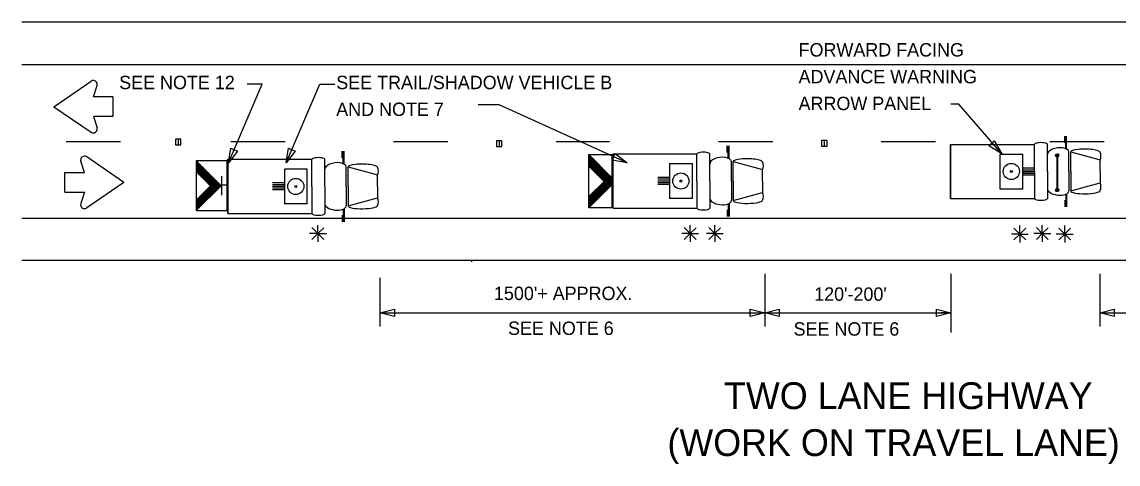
# Model space of a CAD drawing. Extents: x -747 to 834, y -5485 to -3577.
# Drawn here: x -746.8 to -256.3, y -4722 to -4524.1 of the extents above; entities that cross this region are included whole.
import ezdxf

# ---------------------------------------------------------------- set-up
doc = ezdxf.new("R2010")
doc.units = 0
doc.layers.add('Level 1', color=7, linetype='Continuous')
doc.layers.add('Working Level 1', color=7, linetype='Continuous')

msp = doc.modelspace()

# ---------------------------------------------------------------- linework, layer by layer
at = {"layer": 'Level 1'}
for points in [[(-654.31, -4587.26), (-639.27, -4552), (-645.96, -4552)], [(-628.59, -4587.26), (-613.54, -4552), (-606.86, -4552)], [(-476.04, -4587.26), (-533.3, -4561.2), (-542.63, -4561.2)]]:
    msp.add_lwpolyline(points, dxfattribs=at)
at = {"layer": 'Working Level 1'}
for p, q in [((-746.8, -4524.13), (52.95, -4524.13)), ((-746.8, -4543.26), (52.95, -4543.26)), ((-732.53, -4562.09), (-715.86, -4550.65)), ((-714.81, -4557.72), (-713.18, -4552.65)), ((-706.14, -4557.72), (-714.81, -4557.72)), ((-706.14, -4557.72), (-706.14, -4566.45)), ((-732.53, -4562.09), (-715.86, -4573.52)), ((-706.14, -4566.45), (-714.81, -4566.45)), ((-714.81, -4566.45), (-713.18, -4571.53)), ((-280.21, -4578.2), (-280.21, -4575.23)), ((-279.74, -4581.06), (-279.74, -4575.23)), ((-279.35, -4581.06), (-279.35, -4575.23)), ((-675.68, -4576.65), (-678.11, -4576.65)), ((-678.11, -4576.65), (-678.11, -4579.08)), ((-678.11, -4579.08), (-675.68, -4579.08)), ((-676.89, -4576.65), (-676.89, -4579.08)), ((-675.68, -4579.08), (-675.68, -4576.65)), ((-532, -4577.39), (-534.43, -4577.39)), ((-534.43, -4577.39), (-534.43, -4579.82)), ((-534.43, -4579.82), (-532, -4579.82)), ((-533.21, -4577.39), (-533.22, -4579.82)), ((-532, -4579.82), (-532, -4577.39)), ((-431.24, -4582.5), (-431.24, -4579.53)), ((-430.77, -4585.36), (-430.77, -4579.53)), ((-430.38, -4585.36), (-430.38, -4579.53)), ((-386.56, -4577.25), (-388.99, -4577.25)), ((-388.99, -4577.25), (-388.99, -4579.68)), ((-388.99, -4579.68), (-386.56, -4579.68)), ((-387.77, -4577.25), (-387.78, -4579.68)), ((-386.56, -4579.68), (-386.56, -4577.25)), ((-331.27, -4578.92), (-331.27, -4603.18)), ((-331.27, -4578.93), (-293.72, -4578.93)), ((-331.27, -4603.18), (-331.27, -4578.93)), ((-293.72, -4591.05), (-293.72, -4578.93)), ((-287.97, -4591.05), (-287.97, -4578.93)), ((-701.14, -4595.95), (-717.81, -4584.51)), ((-654.6, -4585.63), (-617.05, -4585.63)), ((-654.6, -4609.89), (-654.6, -4585.63)), ((-654.6, -4585.63), (-654.6, -4609.88)), ((-617.05, -4597.76), (-617.05, -4585.63)), ((-611.3, -4597.76), (-611.3, -4585.63)), ((-603.55, -4584.91), (-603.55, -4581.94)), ((-603.08, -4587.76), (-603.08, -4581.94)), ((-602.68, -4587.76), (-602.68, -4581.94)), ((-493.16, -4583.51), (-482.8, -4593.86)), ((-482.3, -4583.23), (-444.75, -4583.23)), ((-482.3, -4607.48), (-482.3, -4583.23)), ((-444.75, -4595.35), (-444.75, -4583.23)), ((-439, -4595.35), (-439, -4583.23)), ((-309.21, -4583.29), (-298.95, -4583.29)), ((-309.21, -4583.29), (-309.21, -4598.81)), ((-298.95, -4598.81), (-298.95, -4583.29)), ((-284.3, -4583.68), (-284.3, -4583.68)), ((-283.68, -4584.03), (-283.68, -4599.08)), ((-283.64, -4584.03), (-283.64, -4599.08)), ((-283.6, -4584.03), (-283.6, -4599.08)), ((-283.52, -4584.03), (-283.52, -4599.08)), ((-283.42, -4583.17), (-283.42, -4583.17)), ((-283.4, -4584.03), (-283.4, -4599.08)), ((-278.33, -4591.05), (-278.33, -4582.32)), ((-277.53, -4582.32), (-264.4, -4585.91)), ((-277.53, -4591.05), (-277.53, -4582.32)), ((-264.4, -4591.05), (-264.4, -4585.91)), ((-718.86, -4591.58), (-720.49, -4586.51)), ((-668.86, -4586.27), (-657.68, -4597.44)), ((-619.12, -4590), (-629.38, -4590)), ((-629.38, -4590), (-629.38, -4605.52)), ((-619.12, -4605.52), (-619.12, -4590)), ((-601.67, -4597.76), (-601.67, -4589.02)), ((-600.87, -4589.02), (-587.74, -4592.61)), ((-600.87, -4597.76), (-600.87, -4589.02)), ((-493.16, -4588.69), (-486.33, -4595.49)), ((-446.82, -4587.59), (-457.08, -4587.59)), ((-457.08, -4587.59), (-457.08, -4603.12)), ((-446.82, -4603.12), (-446.82, -4587.59)), ((-429.36, -4595.35), (-429.36, -4586.62)), ((-428.56, -4586.62), (-415.43, -4590.21)), ((-428.56, -4595.35), (-428.56, -4586.62)), ((-415.43, -4595.35), (-415.43, -4590.21)), ((-298.95, -4589.5), (-293.72, -4589.5)), ((-298.95, -4590.28), (-293.72, -4590.28)), ((-727.53, -4600.31), (-727.53, -4591.58)), ((-727.53, -4591.58), (-718.86, -4591.58)), ((-668.86, -4591.12), (-662.45, -4597.51)), ((-657.3, -4601.65), (-657.3, -4593.24)), ((-587.74, -4597.76), (-587.74, -4592.61)), ((-493.16, -4602.31), (-486.33, -4595.49)), ((-457.08, -4593.8), (-462.31, -4593.8)), ((-457.08, -4594.58), (-462.31, -4594.58)), ((-457.08, -4595.35), (-462.31, -4595.35)), ((-444.75, -4595.35), (-444.75, -4607.48)), ((-439, -4595.35), (-439, -4607.48)), ((-429.36, -4595.35), (-429.36, -4604.09)), ((-428.56, -4595.35), (-428.56, -4604.09)), ((-415.43, -4595.35), (-415.43, -4600.5)), ((-298.95, -4591.05), (-293.72, -4591.05)), ((-298.95, -4591.83), (-293.72, -4591.83)), ((-298.95, -4592.6), (-293.72, -4592.6)), ((-293.72, -4591.05), (-293.72, -4603.18)), ((-287.97, -4591.05), (-287.97, -4603.18)), ((-278.33, -4591.05), (-278.33, -4599.79)), ((-277.53, -4591.05), (-277.53, -4599.79)), ((-264.4, -4591.05), (-264.4, -4596.2)), ((-727.53, -4600.31), (-718.86, -4600.31)), ((-718.86, -4600.31), (-720.49, -4605.38)), ((-701.14, -4595.95), (-717.81, -4607.38)), ((-668.86, -4603.9), (-662.45, -4597.51)), ((-668.8, -4608.57), (-657.68, -4597.44)), ((-654.97, -4597.25), (-657.37, -4597.25)), ((-629.38, -4596.21), (-634.61, -4596.21)), ((-629.38, -4596.98), (-634.61, -4596.98)), ((-629.38, -4597.76), (-634.61, -4597.76)), ((-629.38, -4598.54), (-634.61, -4598.54)), ((-629.38, -4599.31), (-634.61, -4599.31)), ((-617.05, -4597.76), (-617.05, -4609.88)), ((-611.3, -4597.76), (-611.3, -4609.88)), ((-601.67, -4597.76), (-601.67, -4606.49)), ((-600.87, -4597.76), (-600.87, -4606.49)), ((-587.74, -4597.76), (-587.74, -4602.91)), ((-493.1, -4607.29), (-482.85, -4597.04)), ((-457.08, -4596.13), (-462.31, -4596.13)), ((-457.08, -4596.91), (-462.31, -4596.91)), ((-428.56, -4604.09), (-415.43, -4600.5)), ((-309.21, -4598.81), (-298.95, -4598.81)), ((-284.26, -4599.21), (-284.26, -4599.21)), ((-283.38, -4598.7), (-283.38, -4598.7)), ((-277.53, -4599.79), (-264.4, -4596.2)), ((-619.12, -4605.52), (-629.38, -4605.52)), ((-600.87, -4606.49), (-587.74, -4602.91)), ((-446.82, -4603.12), (-457.08, -4603.12)), ((-430.77, -4605.35), (-430.77, -4611.18)), ((-430.38, -4605.35), (-430.38, -4611.18)), ((-331.27, -4603.18), (-293.72, -4603.18)), ((-280.21, -4603.9), (-280.21, -4606.87)), ((-279.74, -4601.05), (-279.74, -4606.87)), ((-279.35, -4601.05), (-279.35, -4606.87)), ((-654.6, -4609.88), (-617.05, -4609.88)), ((-603.08, -4607.76), (-603.08, -4613.58)), ((-602.68, -4607.76), (-602.68, -4613.58)), ((-482.3, -4607.48), (-444.75, -4607.48)), ((-431.24, -4608.21), (-431.24, -4611.18)), ((-746.8, -4611.95), (52.95, -4611.95)), ((-614.35, -4618.83), (-614.35, -4615.06)), ((-603.55, -4610.61), (-603.55, -4613.58)), ((-447.75, -4618.83), (-447.75, -4615.06)), ((-436.78, -4618.83), (-436.78, -4615.06)), ((-300.25, -4619.07), (-300.25, -4615.3)), ((-290.23, -4618.83), (-290.23, -4615.06)), ((-280.2, -4619.07), (-280.2, -4615.3)), ((-614.35, -4618.83), (-618.11, -4618.83)), ((-614.35, -4618.83), (-617.01, -4616.17)), ((-614.35, -4618.83), (-617.01, -4621.49)), ((-614.41, -4618.88), (-611.75, -4616.22)), ((-614.35, -4618.83), (-611.69, -4621.49)), ((-614.35, -4618.83), (-614.35, -4622.59)), ((-614.35, -4618.83), (-610.59, -4618.83)), ((-447.75, -4618.83), (-451.52, -4618.83)), ((-447.75, -4618.83), (-450.41, -4616.17)), ((-447.75, -4618.83), (-450.41, -4621.49)), ((-447.82, -4618.88), (-445.15, -4616.22)), ((-447.75, -4618.83), (-445.09, -4621.49)), ((-447.75, -4618.83), (-447.75, -4622.59)), ((-447.75, -4618.83), (-443.99, -4618.83)), ((-436.78, -4618.83), (-440.54, -4618.83)), ((-436.78, -4618.83), (-439.44, -4616.17)), ((-436.78, -4618.83), (-439.44, -4621.49)), ((-436.84, -4618.88), (-434.18, -4616.22)), ((-436.78, -4618.83), (-434.12, -4621.49)), ((-436.78, -4618.83), (-436.78, -4622.59)), ((-436.78, -4618.83), (-433.02, -4618.83)), ((-300.25, -4619.07), (-304.02, -4619.07)), ((-300.25, -4619.07), (-302.91, -4616.41)), ((-300.25, -4619.07), (-302.91, -4621.73)), ((-300.32, -4619.12), (-297.65, -4616.46)), ((-300.25, -4619.07), (-297.59, -4621.73)), ((-300.25, -4619.07), (-300.25, -4622.83)), ((-300.25, -4619.07), (-296.49, -4619.07)), ((-290.23, -4618.83), (-293.99, -4618.83)), ((-290.23, -4618.83), (-292.89, -4616.17)), ((-290.23, -4618.83), (-292.89, -4621.49)), ((-290.29, -4618.88), (-287.63, -4616.22)), ((-290.23, -4618.83), (-287.57, -4621.49)), ((-290.23, -4618.83), (-290.23, -4622.59)), ((-290.23, -4618.83), (-286.47, -4618.83)), ((-280.2, -4619.07), (-283.97, -4619.07)), ((-280.2, -4619.07), (-282.86, -4616.41)), ((-280.2, -4619.07), (-282.86, -4621.73)), ((-280.27, -4619.12), (-277.6, -4616.46)), ((-280.2, -4619.07), (-277.54, -4621.73)), ((-280.2, -4619.07), (-280.2, -4622.83)), ((-280.2, -4619.07), (-276.44, -4619.07)), ((-746.8, -4630.83), (52.95, -4630.83)), ((-545.32, -4631.43), (-545.81, -4631.43)), ((-586.66, -4638.63), (-586.66, -4660.42)), ((-414.4, -4636.89), (-414.4, -4660.42)), ((-331.11, -4636.89), (-331.11, -4663.07)), ((-264.52, -4636.89), (-264.52, -4660.42)), ((-586.66, -4654.36), (-414.4, -4654.36)), ((-586.66, -4654.36), (-580.9, -4654.36)), ((-414.4, -4654.36), (-415.56, -4654.36)), ((-414.4, -4654.36), (-409.86, -4654.36)), ((-414.4, -4654.36), (-331.11, -4654.36)), ((-331.11, -4654.36), (-335.62, -4654.36)), ((-264.52, -4654.36), (-259.97, -4654.36)), ((-264.43, -4654.36), (-181.13, -4654.36))]:
    msp.add_line(p, q, dxfattribs=at)
for points in [[(-308.41, -4583.15), (-327.51, -4560.97), (-331.15, -4560.97)], [(-726.95, -4577.71), (-702.7, -4577.71)], [(-653.31, -4577.71), (-629.06, -4577.71)], [(-580.56, -4577.71), (-556.3, -4577.71)], [(-507.8, -4577.71), (-483.85, -4577.71)], [(-435.05, -4577.71), (-410.79, -4577.71)], [(-362.29, -4577.71), (-338.04, -4577.71)], [(-286.8, -4577.71), (-262.54, -4577.71)], [(-493.16, -4584.06), (-486.87, -4594.96)], [(-493.16, -4585), (-488.12, -4593.75)], [(-493.16, -4585.94), (-489.36, -4592.53)], [(-492.64, -4584.03), (-484.3, -4598.47)], [(-491.36, -4585.32), (-483.96, -4598.13)], [(-284.32, -4583.94), (-284.06, -4584.4)], [(-284.3, -4583.68), (-283.82, -4584.53)], [(-284.24, -4583.5), (-283.63, -4584.56)], [(-284.15, -4583.36), (-283.47, -4584.55)], [(-284.04, -4583.26), (-283.32, -4584.5)], [(-283.92, -4583.18), (-283.2, -4584.44)], [(-283.78, -4583.14), (-283.09, -4584.34)], [(-283.63, -4583.1), (-282.99, -4584.21)], [(-283.44, -4583.13), (-282.92, -4584.05)], [(-283.23, -4583.21), (-282.88, -4583.82)], [(-668.86, -4586.8), (-662.96, -4597.01)], [(-668.86, -4587.67), (-664.13, -4595.87)], [(-668.86, -4588.55), (-665.3, -4594.73)], [(-668.86, -4589.43), (-666.47, -4593.58)], [(-668.86, -4590.31), (-667.63, -4592.43)], [(-668.36, -4586.76), (-660.55, -4600.31)], [(-667.17, -4587.97), (-660.23, -4599.99)], [(-665.97, -4589.16), (-659.9, -4599.66)], [(-664.77, -4590.36), (-659.58, -4599.35)], [(-493.16, -4586.88), (-490.61, -4591.3)], [(-493.16, -4587.82), (-491.85, -4590.08)], [(-493.16, -4588.75), (-493.1, -4588.86)], [(-490.08, -4586.59), (-483.61, -4597.79)], [(-488.8, -4587.87), (-483.27, -4597.45)], [(-487.52, -4589.15), (-482.93, -4597.11)], [(-486.24, -4590.43), (-482.84, -4596.31)], [(-668.86, -4591.19), (-668.8, -4591.29)], [(-663.58, -4591.56), (-659.26, -4599.02)], [(-662.37, -4592.76), (-658.93, -4598.72)], [(-661.17, -4593.96), (-658.6, -4598.41)], [(-659.97, -4595.15), (-658.3, -4598.05)], [(-486.48, -4595.64), (-484.64, -4598.82)], [(-484.96, -4591.7), (-482.83, -4595.39)], [(-483.69, -4592.97), (-482.81, -4594.49)], [(-665.49, -4600.53), (-663.77, -4603.51)], [(-665.18, -4600.22), (-663.45, -4603.19)], [(-664.85, -4599.89), (-663.12, -4602.88)], [(-664.53, -4599.57), (-662.81, -4602.55)], [(-664.21, -4599.26), (-662.48, -4602.23)], [(-663.88, -4598.93), (-662.16, -4601.91)], [(-663.56, -4598.61), (-661.84, -4601.59)], [(-663.24, -4598.29), (-661.52, -4601.27)], [(-662.92, -4597.96), (-661.19, -4600.95)], [(-662.59, -4597.64), (-660.87, -4600.63)], [(-658.87, -4596.24), (-658, -4597.74)], [(-491.29, -4600.44), (-489.46, -4603.61)], [(-490.95, -4600.1), (-489.12, -4603.26)], [(-490.6, -4599.75), (-488.77, -4602.92)], [(-490.25, -4599.41), (-488.43, -4602.58)], [(-489.91, -4599.06), (-488.08, -4602.24)], [(-489.57, -4598.72), (-487.74, -4601.9)], [(-489.23, -4598.38), (-487.4, -4601.55)], [(-488.88, -4598.04), (-487.05, -4601.21)], [(-488.54, -4597.69), (-486.71, -4600.87)], [(-488.2, -4597.35), (-486.36, -4600.53)], [(-487.86, -4597.01), (-486.02, -4600.19)], [(-487.51, -4596.66), (-485.68, -4599.84)], [(-487.16, -4596.32), (-485.34, -4599.5)], [(-486.83, -4595.98), (-484.99, -4599.16)], [(-284.28, -4599.47), (-284.01, -4599.93)], [(-284.26, -4599.21), (-283.77, -4600.06)], [(-284.2, -4599.03), (-283.59, -4600.09)], [(-284.11, -4598.89), (-283.43, -4600.08)], [(-284, -4598.79), (-283.28, -4600.03)], [(-283.88, -4598.71), (-283.15, -4599.97)], [(-283.74, -4598.67), (-283.04, -4599.87)], [(-283.59, -4598.64), (-282.95, -4599.74)], [(-283.4, -4598.66), (-282.87, -4599.58)], [(-283.19, -4598.74), (-282.84, -4599.35)], [(-668.86, -4604.38), (-667.32, -4607.04)], [(-668.86, -4605.26), (-667.64, -4607.36)], [(-668.71, -4603.75), (-667, -4606.71)], [(-668.39, -4603.43), (-666.67, -4606.4)], [(-668.07, -4603.11), (-666.36, -4606.08)], [(-667.74, -4602.78), (-666.03, -4605.76)], [(-667.43, -4602.47), (-665.71, -4605.43)], [(-667.1, -4602.15), (-665.39, -4605.12)], [(-666.78, -4601.83), (-665.06, -4604.8)], [(-666.46, -4601.5), (-664.74, -4604.48)], [(-666.13, -4601.18), (-664.42, -4604.16)], [(-665.81, -4600.86), (-664.09, -4603.83)], [(-493.16, -4602.81), (-491.52, -4605.66)], [(-493.16, -4603.75), (-491.86, -4606)], [(-493.16, -4604.7), (-492.21, -4606.34)], [(-493, -4602.15), (-491.18, -4605.31)], [(-492.66, -4601.81), (-490.83, -4604.98)], [(-492.32, -4601.47), (-490.49, -4604.63)], [(-491.97, -4601.12), (-490.14, -4604.29)], [(-491.63, -4600.78), (-489.8, -4603.94)], [(-668.86, -4606.14), (-667.96, -4607.68)], [(-668.86, -4607.02), (-668.29, -4608)], [(-668.86, -4607.9), (-668.61, -4608.32)], [(-493.16, -4605.63), (-492.55, -4606.69)], [(-493.16, -4606.57), (-492.9, -4607.02)]]:
    msp.add_lwpolyline(points, dxfattribs=at)
for points in [[(-650.27, -4581.92), (-654.31, -4587.26), (-653.26, -4580.64)], [(-624.54, -4581.92), (-628.59, -4587.26), (-627.53, -4580.64)], [(-311.79, -4577.37), (-308.41, -4583.15), (-314.12, -4579.64)], [(-482.78, -4607.29), (-493.16, -4607.29), (-493.16, -4583.51), (-482.78, -4583.51)], [(-481.28, -4583.09), (-476.04, -4587.26), (-482.63, -4586.05)], [(-668.86, -4586.27), (-668.86, -4608.58), (-654.92, -4608.58), (-654.92, -4586.27)], [(-580.16, -4655.98), (-586.66, -4654.36), (-580.16, -4652.73)], [(-420.9, -4652.73), (-414.4, -4654.36), (-420.9, -4655.98)], [(-407.9, -4655.98), (-414.4, -4654.36), (-407.9, -4652.73)], [(-337.61, -4652.73), (-331.11, -4654.36), (-337.61, -4655.98)], [(-258.02, -4655.98), (-264.52, -4654.36), (-258.02, -4652.73)]]:
    msp.add_lwpolyline(points, close=True, dxfattribs=at)
for centre, radius in [((-283.61, -4583.83), 0.728), ((-304.08, -4591.05), 3.62), ((-304.08, -4591.05), 0.451), ((-624.25, -4597.76), 3.62), ((-451.95, -4595.35), 3.62), ((-451.95, -4595.35), 0.451), ((-624.25, -4597.76), 0.451), ((-283.56, -4599.37), 0.728)]:
    msp.add_circle(centre, radius, dxfattribs=at)
for centre, radius, start, end in [((-714.87, -4552.11), 1.77, 342.1824, 124.4455), ((-714.87, -4572.07), 1.77, 235.5545, 17.8176), ((-718.8, -4585.97), 1.77, 55.5545, 197.8176), ((-267.62, -4584.19), 3.64, 331.8801, 28.1199), ((-590.95, -4590.9), 3.64, 331.8801, 28.1199), ((-418.65, -4588.49), 3.64, 331.8801, 28.1199), ((-418.65, -4602.22), 3.64, 331.8801, 28.1199), ((-267.62, -4597.92), 3.64, 331.8801, 28.1199), ((-718.8, -4605.92), 1.77, 162.1824, 304.4455), ((-590.95, -4604.62), 3.64, 331.8801, 28.1199)]:
    msp.add_arc(centre, radius, start, end, dxfattribs=at)
for centre, major_axis, ratio, start_param, end_param in [((-290.85, -4578.93), (2.88, 0), 0.269913, 0, 3.141593), ((-283.15, -4582.91), (4.82, 0.6), 0.503092, 0, 3.141593), ((-270.97, -4582.39), (6.56, -0.08), 0.2034, 0, 3.141593), ((-614.18, -4585.64), (2.88, 0), 0.269913, 0, 3.141593), ((-441.88, -4583.23), (2.88, 0), 0.269913, 0, 3.141593), ((-434.18, -4587.21), (4.82, 0.6), 0.503092, 0, 3.141593), ((-422, -4586.69), (6.56, -0.08), 0.2034, 0, 3.141593), ((-606.49, -4589.62), (4.82, 0.6), 0.503092, 0, 3.141593), ((-594.3, -4589.1), (6.56, -0.08), 0.2034, 0, 3.141593), ((-283.15, -4599.19), (4.82, -0.6), 0.503092, 3.141593, 6.283185), ((-270.97, -4599.71), (6.56, 0.08), 0.2034, 3.141593, 6.283185), ((-606.49, -4605.9), (4.82, -0.6), 0.503092, 3.141593, 6.283185), ((-434.18, -4603.49), (4.82, -0.6), 0.503092, 3.141593, 6.283185), ((-422, -4604.01), (6.56, 0.08), 0.2034, 3.141593, 6.283185), ((-290.85, -4603.18), (2.88, 0), 0.269913, 3.141593, 6.283185), ((-614.18, -4609.89), (2.88, 0), 0.269913, 3.141593, 6.283185), ((-594.3, -4606.42), (6.56, 0.08), 0.2034, 3.141593, 6.283185), ((-441.88, -4607.48), (2.88, 0), 0.269913, 3.141593, 6.283185)]:
    msp.add_ellipse(centre, major_axis=major_axis, ratio=ratio, start_param=start_param, end_param=end_param, dxfattribs=at)

# ---------------------------------------------------------------- texts
for s, height, p in [('FORWARD FACING', 6, (-399.28, -4539.62)), ('ADVANCE WARNING ', 6, (-399.28, -4551.62)), ('SEE NOTE 12 ', 6, (-703.29, -4554.23)), ('SEE TRAIL/SHADOW VEHICLE B', 6, (-606.16, -4554.23)), ('AND NOTE 7 ', 6, (-606.16, -4566.23)), ('ARROW PANEL', 6, (-399.28, -4563.62)), ("1500'+ APPROX.", 6, (-535.59, -4648.61)), ("120'-200'", 6, (-392.31, -4648.94)), ('SEE NOTE 6', 6, (-529.28, -4664.23)), ('SEE NOTE 6', 6, (-401.5, -4664.55)), ('TWO LANE HIGHWAY', 12, (-432.65, -4697.41)), ('(WORK ON TRAVEL LANE)', 12, (-457.97, -4718.41))]:
    msp.add_text(s, height=height, dxfattribs=at).set_placement(p)

doc.saveas('drawing.dxf')
